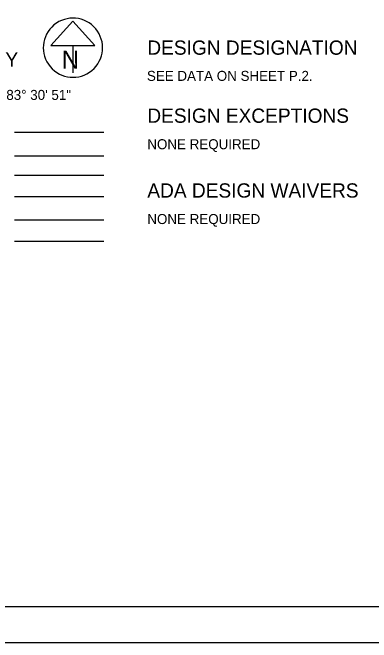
# Model space of a CAD drawing. Extents: x -12 to 164, y -741 to 24.
# Drawn here: x 7.91 to 12.93, y 0 to 8.83 of the extents above; entities that cross this region are included whole.
import ezdxf

# ---------------------------------------------------------------- set-up
doc = ezdxf.new("R2010")
doc.units = 0
for name, color, linetype in [('PM_P_Crosswalk', 7, 'Continuous'), ('SC_Scratch1', 7, 'Continuous'), ('SH_Border', 7, 'Continuous'), ('SH_Cut_Line', 7, 'Continuous'), ('SH_Data', 7, 'Continuous')]:
    doc.layers.add(name, color=color, linetype=linetype)

msp = doc.modelspace()

# ---------------------------------------------------------------- linework, layer by layer
at = {"layer": 'PM_P_Crosswalk'}
msp.add_line((7.9362, 7.152), (9.1862, 7.152), dxfattribs=at)
at = {"layer": 'SH_Border'}
msp.add_lwpolyline([(1.5, 21.5), (33.5, 21.5), (33.5, 0.5), (1.5, 0.5)], close=True, dxfattribs=at)
at = {"layer": 'SH_Cut_Line'}
msp.add_lwpolyline([(0, 0), (34, 0), (34, 22), (0, 22)], close=True, dxfattribs=at)
at = {"layer": 'SH_Data'}
for p, q in [((8.7559, 8.7097), (8.4483, 8.3685)), ((9.0635, 8.3685), (8.7559, 8.7097)), ((8.4483, 8.3685), (9.0635, 8.3685)), ((8.7559, 8.3685), (8.7559, 7.9817)), ((8.7559, 8.336), (8.7559, 8.336)), ((8.7559, 8.336), (8.7559, 8.336)), ((9.1862, 6.8175), (7.9362, 6.8175)), ((9.1862, 6.5458), (7.9362, 6.5458)), ((9.1862, 6.2458), (7.9362, 6.2458)), ((9.1862, 5.919), (7.9362, 5.919)), ((9.1862, 5.619), (7.9362, 5.619))]:
    msp.add_line(p, q, dxfattribs=at)
msp.add_arc((8.7559, 8.336), 0.4148, 129.77984, 129.76332, dxfattribs=at)

# ---------------------------------------------------------------- texts
at = {"layer": 'SC_Scratch1'}
for s, height, p in [('FAYETTE COUNTY', 0.2, (5.5813, 8.0695)), ('SEE DATA ON SHEET P.2.', 0.14, (9.7916, 7.8713)), ('LATITUDE:  39° 31\' 05"     LONGITUDE:  83° 30\' 51"', 0.14, (4.348, 7.6046)), ('DESIGN EXCEPTIONS', 0.2, (9.7972, 7.2834)), ('NONE REQUIRED', 0.14, (9.7972, 6.9133)), ('ADA DESIGN WAIVERS', 0.2, (9.7972, 6.2347)), ('NONE REQUIRED', 0.14, (9.7972, 5.8645))]:
    msp.add_text(s, height=height, dxfattribs=at).set_placement(p)
at = {"layer": 'SH_Data'}
for s, height, p in [('DESIGN DESIGNATION', 0.2, (9.7972, 8.2375)), ('N', 0.25, (8.6006, 8.0446))]:
    msp.add_text(s, height=height, dxfattribs=at).set_placement(p)

doc.saveas('drawing.dxf')
